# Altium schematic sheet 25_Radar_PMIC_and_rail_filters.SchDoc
size 289 x 396 mm
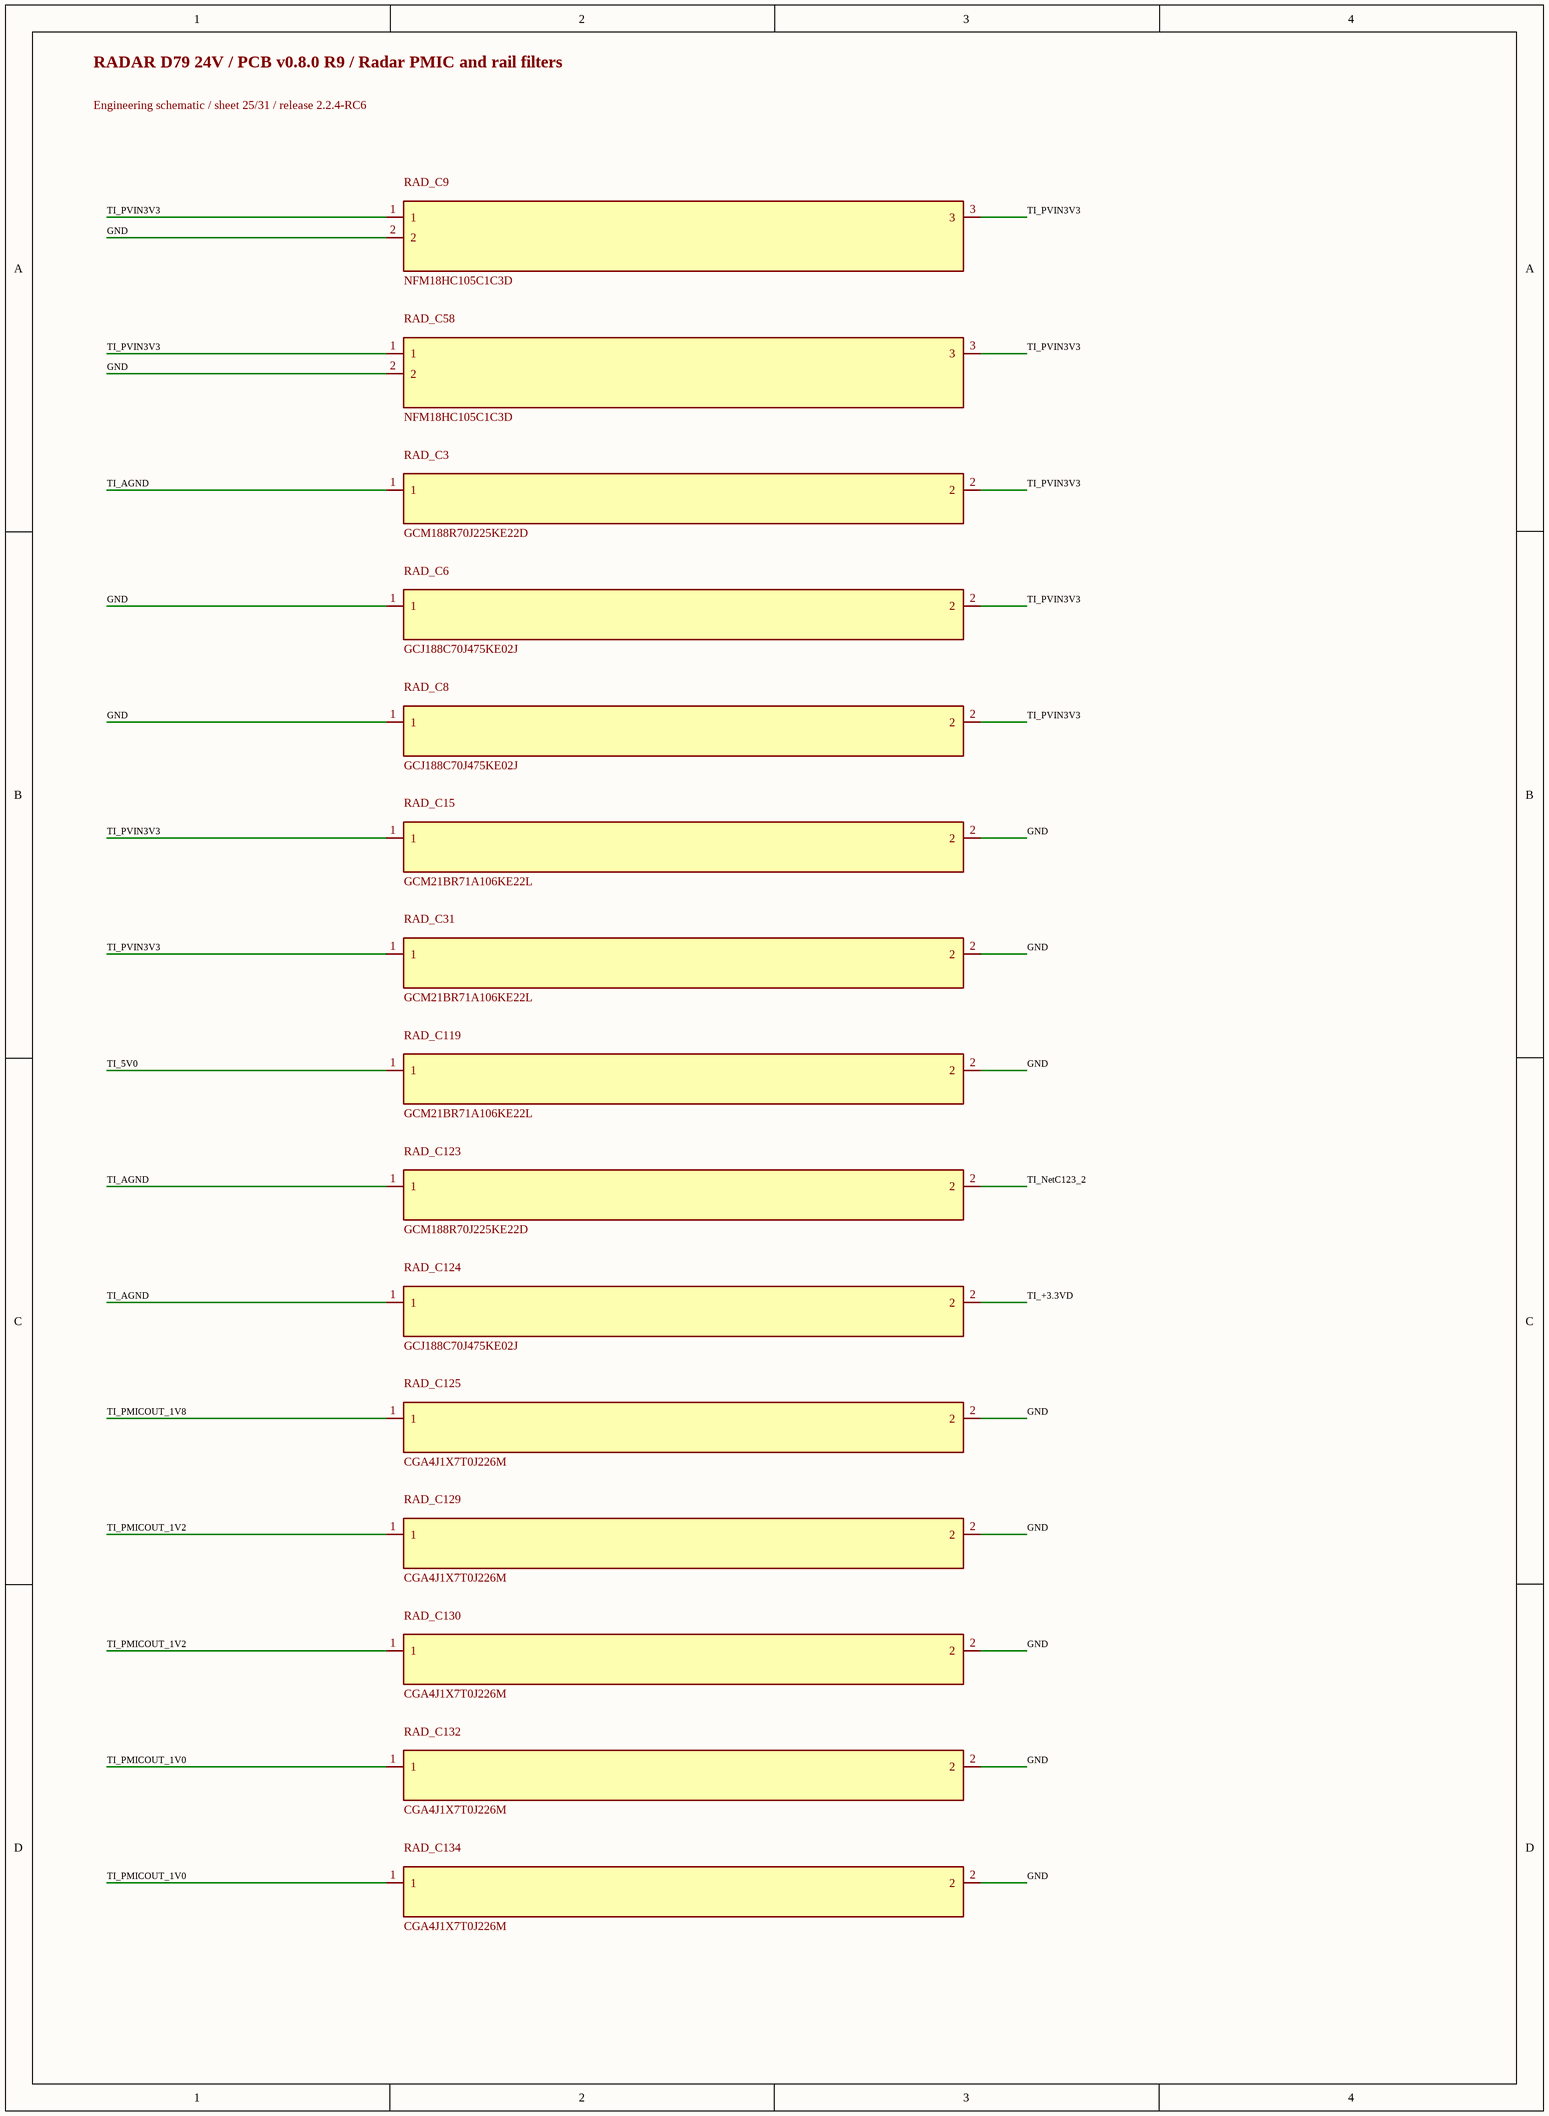
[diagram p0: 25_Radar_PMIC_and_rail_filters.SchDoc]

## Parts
RAD_C3  GCM188R70J225KE22D  [0603L]
RAD_C6  GCJ188C70J475KE02J  [FP-GCJ188C70J475KE02J_0603-MFG]
RAD_C8  GCJ188C70J475KE02J  [FP-GCJ188C70J475KE02J_0603-MFG]
RAD_C9  NFM18HC105C1C3D  [FP-NFM18HC105C1C3D_0603-MFG]
RAD_C15  GCM21BR71A106KE22L  [0805L]
RAD_C31  GCM21BR71A106KE22L  [0805L]
RAD_C58  NFM18HC105C1C3D  [FP-NFM18HC105C1C3D_0603-MFG]
RAD_C119  GCM21BR71A106KE22L  [0805L]
RAD_C123  GCM188R70J225KE22D  [0603L]
RAD_C124  GCJ188C70J475KE02J  [FP-GCJ188C70J475KE02J_0603-MFG]
RAD_C125  CGA4J1X7T0J226M  [0805_155]
RAD_C129  CGA4J1X7T0J226M  [0805_155]
RAD_C130  CGA4J1X7T0J226M  [0805_155]
RAD_C132  CGA4J1X7T0J226M  [0805_155]
RAD_C134  CGA4J1X7T0J226M  [0805_155]

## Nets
GND: RAD_C6.1 RAD_C8.1 RAD_C9.2 RAD_C15.2 RAD_C31.2 RAD_C58.2 RAD_C119.2 RAD_C125.2 RAD_C129.2 RAD_C130.2 RAD_C132.2 RAD_C134.2
TI_5V0: RAD_C119.1
TI_+3.3VD: RAD_C124.2
TI_AGND: RAD_C3.1 RAD_C123.1 RAD_C124.1
TI_NetC123_2: RAD_C123.2
TI_PMICOUT_1V0: RAD_C132.1 RAD_C134.1
TI_PMICOUT_1V2: RAD_C129.1 RAD_C130.1
TI_PMICOUT_1V8: RAD_C125.1
TI_PVIN3V3: RAD_C3.2 RAD_C6.2 RAD_C8.2 RAD_C9.1 RAD_C9.3 RAD_C15.1 RAD_C31.1 RAD_C58.1 RAD_C58.3

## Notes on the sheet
- RADAR D79 24V / PCB v0.8.0 R9 / Radar PMIC and rail filters
- Engineering schematic / sheet 25/31 / release 2.2.4-RC6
